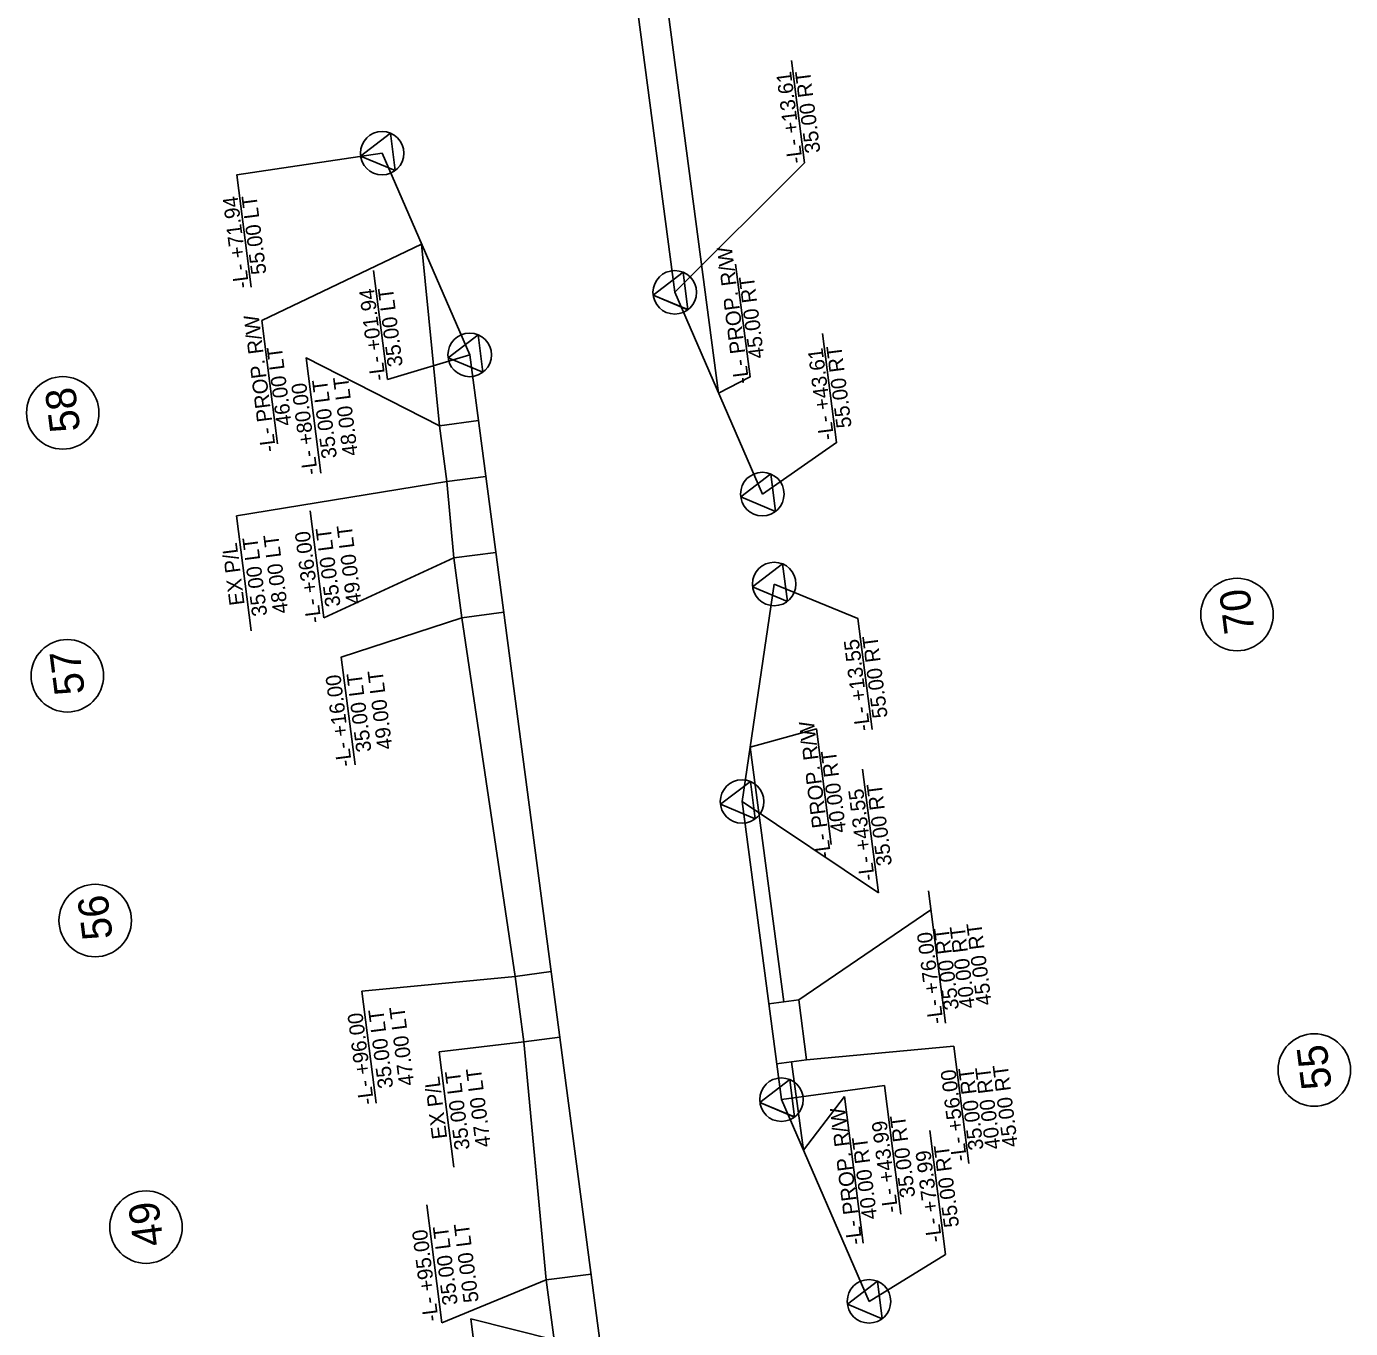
# Model space of a CAD drawing. Extents: x 2368169 to 2369183, y 801414 to 808542.
# Drawn here: x 2368400.1 to 2368838.4, y 806088.8 to 806519.9 of the extents above; entities that cross this region are included whole.
import ezdxf

# ---------------------------------------------------------------- set-up
doc = ezdxf.new("R2010")
doc.units = 0
for name, color, linetype in [('Prop Easement Construction', 7, 'Continuous'), ('Prop Easement Construction Station Offsets', 7, 'Continuous'), ('Prop Easement Permanent Drainage', 7, 'Continuous'), ('Prop Easement Permanent Drainage Station Offsets', 7, 'Continuous'), ('Prop Easement Permanent Drainage Utility', 7, 'Continuous'), ('Prop Easement Permanent Drainage Utility Station Offsets', 7, 'Continuous'), ('Prop Parcel Number CELL', 7, 'Continuous'), ('Prop Parcel Number Text', 7, 'Continuous'), ('Prop ROW Marker CELL', 7, 'Continuous'), ('Prop ROW RW Lines', 7, 'Continuous'), ('Prop ROW Station Offsets', 7, 'Continuous')]:
    doc.layers.add(name, color=color, linetype=linetype)

msp = doc.modelspace()

# ---------------------------------------------------------------- linework, layer by layer
at = {"layer": 'Prop Easement Construction'}
for p, q in [((2368629.17, 806398.45), (2368610, 806543.58)), ((2368536.79, 806387.64), (2368530.86, 806447.83)), ((2368541.56, 806343.89), (2368539.23, 806369.16)), ((2368561.88, 806205.36), (2368544.18, 806324.06)), ((2368650.75, 806196.93), (2368639.61, 806281.24)), ((2368572.14, 806104.84), (2368564.74, 806183.71)), ((2368657.24, 806147.84), (2368653.37, 806177.1))]:
    msp.add_line(p, q, dxfattribs=at)
at = {"layer": 'Prop Easement Construction Station Offsets'}
for p, q in [((2368477.94, 806422.56), (2368530.86, 806447.83)), ((2368483.16, 806381.7), (2368477.94, 806422.56)), ((2368670.84, 806165.55), (2368657.24, 806147.84)), ((2368670.84, 806165.55), (2368677.04, 806117.04))]:
    msp.add_line(p, q, dxfattribs=at)
for points in [[(2368634.82, 806441.14), (2368639.59, 806403.8), (2368629.17, 806398.45)], [(2368666.44, 806249.05), (2368661.56, 806287.28), (2368639.61, 806281.24)]]:
    msp.add_lwpolyline(points, dxfattribs=at)
at = {"layer": 'Prop Easement Permanent Drainage'}
for p, q in [((2368655.71, 806197.58), (2368645.79, 806196.27)), ((2368658.33, 806177.75), (2368655.71, 806197.58)), ((2368658.33, 806177.75), (2368648.41, 806176.45))]:
    msp.add_line(p, q, dxfattribs=at)
at = {"layer": 'Prop Easement Permanent Drainage Station Offsets'}
for p, q in [((2368698.7, 806233.64), (2368704.3, 806189.84)), ((2368699.48, 806227.43), (2368655.71, 806197.58)), ((2368707.1, 806182.22), (2368658.33, 806177.75)), ((2368712.06, 806143.37), (2368707.1, 806182.22))]:
    msp.add_line(p, q, dxfattribs=at)
at = {"layer": 'Prop Easement Permanent Drainage Utility'}
for p, q in [((2368549.68, 806389.35), (2368536.79, 806387.64)), ((2368539.23, 806369.16), (2368536.79, 806387.64)), ((2368552.12, 806370.85), (2368539.23, 806369.16)), ((2368541.56, 806343.89), (2368555.44, 806345.73)), ((2368544.18, 806324.06), (2368541.56, 806343.89)), ((2368544.18, 806324.06), (2368558.06, 806325.9)), ((2368573.78, 806206.93), (2368561.88, 806205.36)), ((2368564.74, 806183.71), (2368561.88, 806205.36)), ((2368576.64, 806185.27), (2368564.74, 806183.71)), ((2368587.01, 806106.8), (2368572.14, 806104.84)), ((2368574.76, 806085.01), (2368572.14, 806104.84))]:
    msp.add_line(p, q, dxfattribs=at)
at = {"layer": 'Prop Easement Permanent Drainage Utility Station Offsets'}
for p, q in [((2368469.57, 806357.87), (2368539.23, 806369.16)), ((2368494.01, 806359.52), (2368498.54, 806324.01)), ((2368474.44, 806319.75), (2368469.57, 806357.87)), ((2368498.54, 806324.01), (2368541.56, 806343.89)), ((2368511.14, 806200.48), (2368561.88, 806205.36)), ((2368511.14, 806200.48), (2368515.88, 806163.34)), ((2368536.72, 806180.33), (2368564.74, 806183.71)), ((2368536.72, 806180.33), (2368541.59, 806142.24)), ((2368537.6, 806090.7), (2368532.62, 806129.71)), ((2368537.6, 806090.7), (2368572.14, 806104.84)), ((2368547.15, 806091.97), (2368574.76, 806085.01)), ((2368547.15, 806091.97), (2368551.9, 806054.83))]:
    msp.add_line(p, q, dxfattribs=at)
for points in [[(2368497.49, 806371.97), (2368492.62, 806410.09), (2368536.79, 806387.64)], [(2368508.84, 806275.37), (2368504.28, 806311.06), (2368544.18, 806324.06)]]:
    msp.add_lwpolyline(points, dxfattribs=at)
at = {"layer": 'Prop Parcel Number CELL'}
for p, q in [((2368412.09, 806391.91), (2368412.09, 806391.91)), ((2368800.8, 806325.15), (2368800.8, 806325.15)), ((2368413.61, 806304.88), (2368413.61, 806304.88)), ((2368422.84, 806223.85), (2368422.84, 806223.85)), ((2368826.37, 806174.36), (2368826.37, 806174.36)), ((2368439.66, 806122.34), (2368439.66, 806122.34))]:
    msp.add_line(p, q, dxfattribs=at)
for centre in [(2368412.09, 806391.91), (2368800.8, 806325.15), (2368413.61, 806304.88), (2368422.84, 806223.85), (2368826.37, 806174.36), (2368439.66, 806122.34)]:
    msp.add_circle(centre, 12, dxfattribs=at)
at = {"layer": 'Prop ROW Marker CELL'}
for p, q in [((2368517.81, 806477.88), (2368517.81, 806477.88)), ((2368517.81, 806477.88), (2368517.81, 806477.88)), ((2368614.67, 806431.84), (2368614.67, 806431.84)), ((2368614.67, 806431.84), (2368614.67, 806431.84)), ((2368546.8, 806411.1), (2368546.8, 806411.1)), ((2368546.8, 806411.1), (2368546.8, 806411.1)), ((2368643.67, 806365.05), (2368643.67, 806365.05)), ((2368643.67, 806365.05), (2368643.67, 806365.05)), ((2368647.61, 806335.26), (2368647.61, 806335.26)), ((2368647.61, 806335.26), (2368647.61, 806335.26)), ((2368636.95, 806263.24), (2368636.95, 806263.24)), ((2368636.95, 806263.24), (2368636.95, 806263.24)), ((2368649.99, 806164.54), (2368649.99, 806164.54)), ((2368649.99, 806164.54), (2368649.99, 806164.54)), ((2368678.98, 806097.76), (2368678.98, 806097.76)), ((2368678.98, 806097.76), (2368678.98, 806097.76))]:
    msp.add_line(p, q, dxfattribs=at)
for points in [[(2368522.17, 806472.13), (2368510.66, 806476.96), (2368520.59, 806484.53)], [(2368522.18, 806472.14), (2368510.67, 806476.96), (2368520.58, 806484.54)], [(2368619.04, 806426.1), (2368607.53, 806430.92), (2368617.44, 806438.49)], [(2368619.03, 806426.09), (2368607.53, 806430.92), (2368617.45, 806438.49)], [(2368551.17, 806405.36), (2368539.66, 806410.18), (2368549.57, 806417.76)], [(2368551.17, 806405.35), (2368539.66, 806410.19), (2368549.58, 806417.75)], [(2368648.04, 806359.32), (2368636.53, 806364.13), (2368646.44, 806371.71)], [(2368648.03, 806359.31), (2368636.53, 806364.14), (2368646.45, 806371.71)], [(2368651.97, 806329.52), (2368640.46, 806334.34), (2368650.38, 806341.92)], [(2368651.97, 806329.51), (2368640.46, 806334.35), (2368650.38, 806341.91)], [(2368641.31, 806257.5), (2368629.8, 806262.33), (2368639.73, 806269.9)], [(2368641.32, 806257.5), (2368629.81, 806262.32), (2368639.72, 806269.9)], [(2368654.35, 806158.79), (2368642.84, 806163.63), (2368652.77, 806171.19)], [(2368654.36, 806158.8), (2368642.85, 806163.62), (2368652.76, 806171.2)], [(2368683.35, 806092.02), (2368671.84, 806096.84), (2368681.76, 806104.42)], [(2368683.35, 806092.01), (2368671.84, 806096.85), (2368681.76, 806104.41)]]:
    msp.add_lwpolyline(points, close=True, dxfattribs=at)
for centre in [(2368517.81, 806477.88), (2368614.67, 806431.84), (2368546.8, 806411.1), (2368643.67, 806365.05), (2368647.61, 806335.26), (2368636.95, 806263.24), (2368649.99, 806164.54), (2368678.98, 806097.76)]:
    msp.add_circle(centre, 7.2, dxfattribs=at)
at = {"layer": 'Prop ROW RW Lines'}
for p, q in [((2368614.67, 806431.84), (2368590.85, 806612.17)), ((2368517.81, 806477.88), (2368546.8, 806411.1)), ((2368643.67, 806365.05), (2368614.67, 806431.84)), ((2368596.48, 806035.12), (2368546.8, 806411.1)), ((2368647.61, 806335.26), (2368636.95, 806263.24)), ((2368649.99, 806164.54), (2368636.95, 806263.24)), ((2368678.98, 806097.76), (2368649.99, 806164.54))]:
    msp.add_line(p, q, dxfattribs=at)
at = {"layer": 'Prop ROW Station Offsets'}
for p, q in [((2368653.35, 806508.56), (2368657.68, 806474.67)), ((2368657.68, 806474.67), (2368614.67, 806431.84)), ((2368519.58, 806403.02), (2368514.97, 806439.11)), ((2368519.58, 806403.02), (2368546.8, 806411.1)), ((2368676.86, 806274.01), (2368682.09, 806233.04)), ((2368682.09, 806233.04), (2368636.95, 806263.24)), ((2368684.07, 806169.28), (2368649.99, 806164.54)), ((2368689.51, 806126.65), (2368684.07, 806169.28))]:
    msp.add_line(p, q, dxfattribs=at)
for points in [[(2368474.44, 806433.59), (2368469.7, 806470.7), (2368517.81, 806477.88)], [(2368663.63, 806418.17), (2368668.24, 806382.08), (2368643.67, 806365.05)], [(2368680.03, 806287.06), (2368675.33, 806323.82), (2368647.61, 806335.26)], [(2368699.1, 806154.37), (2368704.34, 806113.32), (2368678.98, 806097.76)]]:
    msp.add_lwpolyline(points, dxfattribs=at)

# ---------------------------------------------------------------- texts
at = {"layer": 'Prop Easement Construction Station Offsets'}
for s, p in [('-L- PROP. R/W', (2368639.33, 806401.82)), ('45.00 RT', (2368644.32, 806410.17)), ('-L- PROP. R/W', (2368482.7, 806379.25)), ('46.00 LT', (2368487.9, 806387.92)), ('-L- PROP. R/W', (2368666.48, 806244.79)), ('40.00 RT', (2368671.46, 806253.14)), ('-L- PROP. R/W', (2368676.76, 806116.83)), ('40.00 RT', (2368681.74, 806125.18))]:
    msp.add_text(s, height=5, rotation=97.2784, dxfattribs=at).set_placement(p)
at = {"layer": 'Prop Easement Permanent Drainage Station Offsets'}
for s, p in [('45.00 RT', (2368719.63, 806196.07)), ('-L- +76.00', (2368703.63, 806189.91)), ('35.00 RT', (2368708.78, 806194.51)), ('40.00 RT', (2368714.11, 806195.03)), ('-L- +56.00', (2368711.45, 806144.39)), ('35.00 RT', (2368716.96, 806148.12)), ('40.00 RT', (2368722.53, 806148.38)), ('45.00 RT', (2368728.31, 806149.11))]:
    msp.add_text(s, height=5, rotation=97.2784, dxfattribs=at).set_placement(p)
at = {"layer": 'Prop Easement Permanent Drainage Utility Station Offsets'}
for s, p in [('35.00 LT', (2368502.89, 806377.09)), ('48.00 LT', (2368509.83, 806377.98)), ('-L- +80.00', (2368496.52, 806371.7)), ('49.00 LT', (2368511.03, 806328.88)), ('35.00 LT', (2368479.83, 806324.87)), ('48.00 LT', (2368486.77, 806325.76)), ('-L- +36.00', (2368497.71, 806322.61)), ('35.00 LT', (2368504.08, 806328)), ('EX P/L', (2368472.31, 806328.49)), ('35.00 LT', (2368514.31, 806279.89)), ('49.00 LT', (2368521.25, 806280.78)), ('-L- +16.00', (2368507.86, 806275.1)), ('-L- +96.00', (2368515.14, 806163.16)), ('35.00 LT', (2368521.51, 806168.55)), ('47.00 LT', (2368528.45, 806169.44)), ('47.00 LT', (2368553.82, 806149.07)), ('EX P/L', (2368539.36, 806151.79)), ('35.00 LT', (2368546.88, 806148.18)), ('-L- +95.00', (2368536.51, 806091.4)), ('35.00 LT', (2368542.88, 806096.79)), ('50.00 LT', (2368549.82, 806097.67))]:
    msp.add_text(s, height=5, rotation=97.2784, dxfattribs=at).set_placement(p)
at = {"layer": 'Prop Parcel Number Text'}
for s, p in [('58', (2368417.94, 806386.11)), ('70', (2368806.65, 806319.41)), ('57', (2368419.46, 806299.1)), ('56', (2368428.69, 806218.06)), ('55', (2368832.22, 806168.51)), ('49', (2368445.51, 806116.54))]:
    msp.add_text(s, height=10, rotation=97.2784, dxfattribs=at).set_placement(p)
at = {"layer": 'Prop ROW Station Offsets'}
for s, p in [('-L- +13.61', (2368657.04, 806474.77)), ('35.00 RT', (2368662.9, 806478.19)), ('-L- +71.94', (2368473.82, 806433.47)), ('55.00 LT', (2368479.54, 806438.03)), ('-L- +01.94', (2368518.97, 806402.9)), ('35.00 LT', (2368524.68, 806407.47)), ('-L- +43.61', (2368667.47, 806383.2)), ('55.00 RT', (2368673.26, 806387.22)), ('-L- +13.55', (2368679.42, 806286.85)), ('55.00 RT', (2368685.17, 806291.16)), ('-L- +43.55', (2368680.92, 806237.32)), ('35.00 RT', (2368686.59, 806242.22)), ('-L- +43.99', (2368688.65, 806127.42)), ('35.00 RT', (2368694.32, 806132.38)), ('55.00 RT', (2368708.83, 806122.56)), ('-L- +73.99', (2368703.16, 806117.61))]:
    msp.add_text(s, height=5, rotation=97.2784, dxfattribs=at).set_placement(p)

doc.saveas('drawing.dxf')
